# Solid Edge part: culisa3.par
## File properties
Author: Ionut
Template: Normal.par
Last saved by: Ionut
Revision: 3
Application: Solid Edge
Density: 7800.000 kg/m^3
Accuracy: 0.010
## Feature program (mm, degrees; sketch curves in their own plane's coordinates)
sketch for "unnamed Protrusion 1" plane through (0, 0, 0) normal (0, 0, 1) x-axis (1, 0, 0)
  line (-6, -50.2933) -> (6, -50.2933)
  line (6, -50.2933) -> (6, 49.7067)
  line (6, 49.7067) -> (-6, 49.7067)
  line (-6, 49.7067) -> (-6, -50.2933)
  dimension (linear) = 6
  dimension (linear) = 6
extrude "unnamed Protrusion 1" add finite 3 along +normal
sketch for "ExtrudedCutout_1" plane through (0, -0.2933, 3) normal (0, 0, 1) x-axis (0, 1, 0)
  line (-39.7067, -2) -> (40.2933, -2)
  line (40.2933, -2) -> (40.2933, 2)
  line (40.2933, 2) -> (-39.7067, 2)
  line (-39.7067, 2) -> (-39.7067, -2)
  dimension (linear) = 40.2933
  dimension (linear) = 39.7067
extrude "ExtrudedCutout_1" cut finite 59.8469 along -normal
fillet "Round_1" radius 6
fillet "Round_2" radius 2
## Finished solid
Body 1: solid body, 10 faces, 24 edges, 16 vertices.
  Faces by surface: plane 6, cylinder 4
  Edges by curve: line 16, circle 8
Bounding box of the edges (mm): 12.000 x 100.000 x 3.000, from (-6, -50.2933, 0) to (6, 49.7067, 3).
Cylindrical faces by radius (mm): R2 x2, R6 x2
Planar faces by outward normal: +x 2, +z 1, -x 2, -z 1
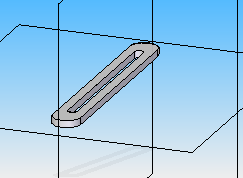
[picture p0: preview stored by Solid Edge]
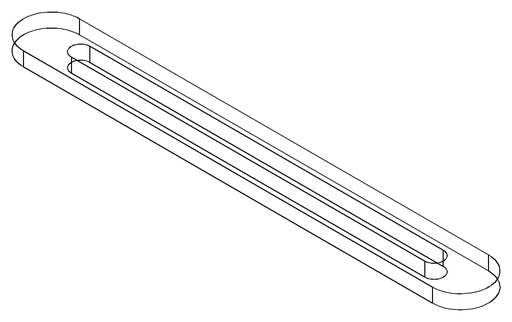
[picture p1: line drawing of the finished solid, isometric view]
